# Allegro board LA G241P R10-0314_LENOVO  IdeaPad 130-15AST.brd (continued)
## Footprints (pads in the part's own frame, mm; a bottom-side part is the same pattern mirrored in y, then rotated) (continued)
A6-9200E_BGA_769P-T
  round 0.406 smd: A2(0.6,0) A3(1.35,0) A39(21.25,0) A40(22,0) AA4(2.1,-11.3) AA5(2.9,-11.3) AA7(3.7,-11.3) AA8(4.5,-11.3) AA10(5.3,-11.3) AA11(6.3,-11.3) AA13(7.3,-11.3) AA15(8.3,-11.3) AA17(9.3,-11.3) AA19(10.3,-11.3) AA21(11.3,-11.3) AA23(12.3,-11.3) AA25(13.3,-11.3) AA27(14.3,-11.3) AA29(15.3,-11.3) AA31(16.3,-11.3) AA32(17.3,-11.3) AA34(18.1,-11.3) AA35(18.9,-11.3) AA37(19.7,-11.3) AA38(20.5,-11.3) AC4(2.1,-12.4) AC5(2.9,-12.4) AC7(3.7,-12.4) AC8(4.5,-12.4) AC10(5.3,-12.4) AC11(6.3,-12.3) AC13(7.3,-12.3) AC15(8.3,-12.3) AC17(9.3,-12.3) AC19(10.3,-12.3) AC21(11.3,-12.3) AC23(12.3,-12.3) AC25(13.3,-12.3) AC27(14.3,-12.3) AC29(15.3,-12.3) AC31(16.3,-12.3) AC32(17.3,-12.4) AC34(18.1,-12.4) AC35(18.9,-12.4) AC37(19.7,-12.4) AC38(20.5,-12.4) AE4(2.1,-13.5) AE5(2.9,-13.5) AE7(3.7,-13.5) AE8(4.5,-13.5) AE10(5.3,-13.5) AE11(6.3,-13.3) AE13(7.3,-13.3) AE15(8.3,-13.3) AE17(9.3,-13.3) AE19(10.3,-13.3) AE21(11.3,-13.3) AE23(12.3,-13.3) AE25(13.3,-13.3) AE27(14.3,-13.3) AE29(15.3,-13.3) AE31(16.3,-13.3) AE32(17.3,-13.5) AE34(18.1,-13.5) AE35(18.9,-13.5) AE37(19.7,-13.5) AE38(20.5,-13.5) AG4(2.1,-14.6) AG5(2.9,-14.6) AG7(3.7,-14.6) AG8(4.5,-14.6) AG10(5.3,-14.6) AG11(6.3,-14.3) AG13(7.3,-14.3) AG15(8.3,-14.3) AG17(9.3,-14.3) AG19(10.3,-14.3) AG21(11.3,-14.3) AG23(12.3,-14.3) AG25(13.3,-14.3) AG27(14.3,-14.3) AG29(15.3,-14.3) AG31(16.3,-14.3) AG32(17.3,-14.6) AG34(18.1,-14.6) AG35(18.9,-14.6) AG37(19.7,-14.6) AG38(20.5,-14.6) AJ4(2.1,-15.7) AJ5(2.9,-15.7) AJ7(3.7,-15.7) AJ8(4.5,-15.7) AJ10(5.3,-15.7) AJ11(6.3,-15.3) AJ13(7.3,-15.3) AJ15(8.3,-15.3) AJ17(9.3,-15.3) AJ19(10.3,-15.3) AJ21(11.3,-15.3) AJ23(12.3,-15.3) AJ25(13.3,-15.3) AJ27(14.3,-15.3) AJ29(15.3,-15.3) AJ31(16.3,-15.3) AJ32(17.3,-15.7) AJ34(18.1,-15.7) AJ35(18.9,-15.7) AJ37(19.7,-15.7) AJ38(20.5,-15.7) AL4(2.1,-16.8) AL5(2.9,-16.8) AL7(3.7,-16.8) AL8(4.5,-16.8) AL10(5.3,-16.8) AL11(6.3,-16.3) AL13(7.3,-16.3) AL15(8.3,-16.3) AL17(9.3,-16.3) AL19(10.3,-16.3) AL21(11.3,-16.3) AL23(12.3,-16.3) AL25(13.3,-16.3) AL27(14.3,-16.3) AL29(15.3,-16.3) AL31(16.3,-16.3) AL32(17.3,-16.8) AL34(18.1,-16.8) AL35(18.9,-16.8) AL37(19.7,-16.8) AL38(20.5,-16.8) AM11(5.8,-17.3) AM13(6.9,-17.3) AM15(8,-17.3) AM17(9.1,-17.3) AM19(10.2,-17.3) AM21(11.3,-17.3) AM23(12.4,-17.3) AM25(13.5,-17.3) AM27(14.6,-17.3) AM29(15.7,-17.3) AM31(16.8,-17.3) AN4(2.1,-17.9) AN5(2.9,-17.9) AN7(3.7,-17.9) AN8(4.5,-17.9) AN34(18.1,-17.9) AN35(18.9,-17.9) AN37(19.7,-17.9) AN38(20.5,-17.9) AP11(5.8,-18.1) AP13(6.9,-18.1) AP15(8,-18.1) AP17(9.1,-18.1) AP19(10.2,-18.1) AP21(11.3,-18.1) AP23(12.4,-18.1) AP25(13.5,-18.1) AP27(14.6,-18.1) AP29(15.7,-18.1) AP31(16.8,-18.1) AR4(2.1,-19) AR5(2.9,-19) AR7(3.7,-19) AR11(5.8,-18.9) AR13(6.9,-18.9) AR15(8,-18.9) AR17(9.1,-18.9) AR19(10.2,-18.9) AR21(11.3,-18.9) AR23(12.4,-18.9) AR25(13.5,-18.9) AR27(14.6,-18.9) AR29(15.7,-18.9) AR31(16.8,-18.9) AR35(18.9,-19) AR37(19.7,-19) AR38(20.5,-19) AU4(2.1,-20.1) AU7(3.6,-19.7) AU9(4.7,-19.7) AU11(5.8,-19.7) AU13(6.9,-19.7) AU15(8,-19.7) AU17(9.1,-19.7) AU19(10.2,-19.7) AU21(11.3,-19.7) AU23(12.4,-19.7) AU25(13.5,-19.7) AU27(14.6,-19.7) AU29(15.7,-19.7) AU31(16.8,-19.7) AU33(17.9,-19.7) AU35(19,-19.7) AU38(20.5,-20.1) AV7(3.6,-20.5) AV9(4.7,-20.5) AV11(5.8,-20.5) AV13(6.9,-20.5) AV15(8,-20.5) AV17(9.1,-20.5) AV19(10.2,-20.5) AV21(11.3,-20.5) AV23(12.4,-20.5) AV25(13.5,-20.5) AV27(14.6,-20.5) AV29(15.7,-20.5) AV31(16.8,-20.5) AV33(17.9,-20.5) AV35(19,-20.5) AW1(0,-21.25) AW41(22.6,-21.25) AY1(0,-22) AY2(0.7,-21.9) AY40(21.9,-21.9) AY41(22.6,-22) B1(0,-0.6) B2(0.7,-0.7) B40(21.9,-0.7) B41(22.6,-0.6) BA2(0.6,-22.6) BA3(1.35,-22.6) BA39(21.25,-22.6) BA40(22,-22.6) C1(0,-1.35) C41(22.6,-1.35) D7(3.6,-2.1) D9(4.7,-2.1) D11(5.8,-2.1) D13(6.9,-2.1) D15(8,-2.1) D17(9.1,-2.1) D19(10.2,-2.1) D21(11.3,-2.1) D23(12.4,-2.1) D25(13.5,-2.1) D27(14.6,-2.1) D29(15.7,-2.1) D31(16.8,-2.1) D33(17.9,-2.1) D35(19,-2.1) E4(2.1,-2.5) E7(3.6,-2.9) E9(4.7,-2.9) E11(5.8,-2.9) E13(6.9,-2.9) E15(8,-2.9) E17(9.1,-2.9) E19(10.2,-2.9) E21(11.3,-2.9) E23(12.4,-2.9) E25(13.5,-2.9) E27(14.6,-2.9) E29(15.7,-2.9) E31(16.8,-2.9) E33(17.9,-2.9) E35(19,-2.9) E38(20.5,-2.5) G4(2.1,-3.6) G5(2.9,-3.6) G7(3.7,-3.6) G11(5.8,-3.7) G13(6.9,-3.7) G15(8,-3.7) G17(9.1,-3.7) G19(10.2,-3.7) G21(11.3,-3.7) G23(12.4,-3.7) G25(13.5,-3.7) G27(14.6,-3.7) G29(15.7,-3.7) G31(16.8,-3.7) G35(18.9,-3.6) G37(19.7,-3.6) G38(20.5,-3.6) H11(5.8,-4.5) H13(6.9,-4.5) H15(8,-4.5) H17(9.1,-4.5) H19(10.2,-4.5) H21(11.3,-4.5) H23(12.4,-4.5) H25(13.5,-4.5) H27(14.6,-4.5) H29(15.7,-4.5) H31(16.8,-4.5) J4(2.1,-4.7) J5(2.9,-4.7) J7(3.7,-4.7) J8(4.5,-4.7) J34(18.1,-4.7) J35(18.9,-4.7) J37(19.7,-4.7) J38(20.5,-4.7) K11(5.8,-5.3) K13(6.9,-5.3) K15(8,-5.3) K17(9.1,-5.3) K19(10.2,-5.3) K21(11.3,-5.3) K23(12.4,-5.3) K25(13.5,-5.3) K27(14.6,-5.3) K29(15.7,-5.3) K31(16.8,-5.3) L4(2.1,-5.8) L5(2.9,-5.8) L7(3.7,-5.8) L8(4.5,-5.8) L10(5.3,-5.8) L11(6.3,-6.3) L13(7.3,-6.3) L15(8.3,-6.3) L17(9.3,-6.3) L19(10.3,-6.3) L21(11.3,-6.3) L23(12.3,-6.3) L25(13.3,-6.3) L27(14.3,-6.3) L29(15.3,-6.3) L31(16.3,-6.3) L32(17.3,-5.8) L34(18.1,-5.8) L35(18.9,-5.8) L37(19.7,-5.8) L38(20.5,-5.8) N4(2.1,-6.9) N5(2.9,-6.9) N7(3.7,-6.9) N8(4.5,-6.9) N10(5.3,-6.9) N11(6.3,-7.3) N13(7.3,-7.3) N15(8.3,-7.3) N17(9.3,-7.3) N19(10.3,-7.3) N21(11.3,-7.3) N23(12.3,-7.3) N25(13.3,-7.3) N27(14.3,-7.3) N29(15.3,-7.3) N31(16.3,-7.3) N32(17.3,-6.9) N34(18.1,-6.9) N35(18.9,-6.9) N37(19.7,-6.9) N38(20.5,-6.9) R4(2.1,-8) R5(2.9,-8) R7(3.7,-8) R8(4.5,-8) R10(5.3,-8) R11(6.3,-8.3) R13(7.3,-8.3) R15(8.3,-8.3) R17(9.3,-8.3) R19(10.3,-8.3) R21(11.3,-8.3) R23(12.3,-8.3) R25(13.3,-8.3) R27(14.3,-8.3) R29(15.3,-8.3) R31(16.3,-8.3) R32(17.3,-8) R34(18.1,-8) R35(18.9,-8) R37(19.7,-8) R38(20.5,-8) U4(2.1,-9.1) U5(2.9,-9.1) U7(3.7,-9.1) U8(4.5,-9.1) U10(5.3,-9.1) U11(6.3,-9.3) U13(7.3,-9.3) U15(8.3,-9.3) U17(9.3,-9.3) U19(10.3,-9.3) U21(11.3,-9.3) U23(12.3,-9.3) U25(13.3,-9.3) U27(14.3,-9.3) U29(15.3,-9.3) U31(16.3,-9.3) U32(17.3,-9.1) U34(18.1,-9.1) U35(18.9,-9.1) U37(19.7,-9.1) U38(20.5,-9.1) W4(2.1,-10.2) W5(2.9,-10.2) W7(3.7,-10.2) W8(4.5,-10.2) W10(5.3,-10.2) W11(6.3,-10.3) W13(7.3,-10.3) W15(8.3,-10.3) W17(9.3,-10.3) W19(10.3,-10.3) W21(11.3,-10.3) W23(12.3,-10.3) W25(13.3,-10.3) W27(14.3,-10.3) W29(15.3,-10.3) W31(16.3,-10.3) W32(17.3,-10.2) W34(18.1,-10.2) W35(18.9,-10.2) W37(19.7,-10.2) W38(20.5,-10.2)
  round 0.305 smd: A4(1.95,-0.35) A5(2.5,0) A6(3.05,-0.35) A7(3.6,0) A8(4.15,-0.35) A9(4.7,0) A10(5.25,-0.35) A11(5.8,0) A12(6.35,-0.35) A13(6.9,0) A14(7.45,-0.35) A15(8,0) A16(8.55,-0.35) A17(9.1,0) A18(9.65,-0.35) A19(10.2,0) A20(10.75,-0.35) A21(11.3,0) A22(11.85,-0.35) A23(12.4,0) A24(12.95,-0.35) A25(13.5,0) A26(14.05,-0.35) A27(14.6,0) A28(15.15,-0.35) A29(15.7,0) A30(16.25,-0.35) A31(16.8,0) A32(17.35,-0.35) A33(17.9,0) A34(18.45,-0.35) A35(19,0) A36(19.55,-0.35) A37(20.1,0) A38(20.65,-0.35) AA1(0,-11.3) AA2(0.7,-11.3) AA3(1.4,-11.3) AA39(21.2,-11.3) AA40(21.9,-11.3) AA41(22.6,-11.3) AB1(0.35,-11.85) AB2(1.05,-11.85) AB40(21.55,-11.85) AB41(22.25,-11.85) AC1(0,-12.4) AC2(0.7,-12.4) AC3(1.4,-12.4) AC39(21.2,-12.4) AC40(21.9,-12.4) AC41(22.6,-12.4) AD1(0.35,-12.95) AD2(1.05,-12.95) AD40(21.55,-12.95) AD41(22.25,-12.95) AE1(0,-13.5) AE2(0.7,-13.5) AE3(1.4,-13.5) AE39(21.2,-13.5) AE40(21.9,-13.5) AE41(22.6,-13.5) AF1(0.35,-14.05) AF2(1.05,-14.05) AF40(21.55,-14.05) AF41(22.25,-14.05) AG1(0,-14.6) AG2(0.7,-14.6) AG3(1.4,-14.6) AG39(21.2,-14.6) AG40(21.9,-14.6) AG41(22.6,-14.6) AH1(0.35,-15.15) AH2(1.05,-15.15) AH40(21.55,-15.15) AH41(22.25,-15.15) AJ1(0,-15.7) AJ2(0.7,-15.7) AJ3(1.4,-15.7) AJ39(21.2,-15.7) AJ40(21.9,-15.7) AJ41(22.6,-15.7) AK1(0.35,-16.25) AK2(1.05,-16.25) AK40(21.55,-16.25) AK41(22.25,-16.25) AL1(0,-16.8) AL2(0.7,-16.8) AL3(1.4,-16.8) AL39(21.2,-16.8) AL40(21.9,-16.8) AL41(22.6,-16.8) AM1(0.35,-17.35) AM2(1.05,-17.35) AM40(21.55,-17.35) AM41(22.25,-17.35) AN1(0,-17.9) AN2(0.7,-17.9) AN3(1.4,-17.9) AN39(21.2,-17.9) AN40(21.9,-17.9) AN41(22.6,-17.9) AP1(0.35,-18.45) AP2(1.05,-18.45) AP40(21.55,-18.45) AP41(22.25,-18.45) AR1(0,-19) AR2(0.7,-19) AR3(1.4,-19) AR39(21.2,-19) AR40(21.9,-19) AR41(22.6,-19) AT1(0.35,-19.55) AT2(1.05,-19.55) AT40(21.55,-19.55) AT41(22.25,-19.55) AU1(0,-20.1) AU2(0.7,-20.1) AU3(1.4,-20.1) AU39(21.2,-20.1) AU40(21.9,-20.1) AU41(22.6,-20.1) AV1(0.35,-20.65) AV2(1.05,-20.65) AV40(21.55,-20.65) AV41(22.25,-20.65) AW2(0.7,-21.2) AW3(1.4,-21.2) AW5(2.5,-21.2) AW7(3.6,-21.2) AW9(4.7,-21.2) AW11(5.8,-21.2) AW13(6.9,-21.2) AW15(8,-21.2) AW17(9.1,-21.2) AW19(10.2,-21.2) AW21(11.3,-21.2) AW23(12.4,-21.2) AW25(13.5,-21.2) AW27(14.6,-21.2) AW29(15.7,-21.2) AW31(16.8,-21.2) AW33(17.9,-21.2) AW35(19,-21.2) AW37(20.1,-21.2) AW39(21.2,-21.2) AW40(21.9,-21.2) AY3(1.4,-21.9) AY4(1.95,-21.55) AY5(2.5,-21.9) AY6(3.05,-21.55) AY7(3.6,-21.9) AY8(4.15,-21.55) AY9(4.7,-21.9) AY10(5.25,-21.55) AY11(5.8,-21.9) AY12(6.35,-21.55) AY13(6.9,-21.9) AY14(7.45,-21.55) AY15(8,-21.9) AY16(8.55,-21.55) AY17(9.1,-21.9) AY18(9.65,-21.55) AY19(10.2,-21.9) AY20(10.75,-21.55) AY21(11.3,-21.9) AY22(11.85,-21.55) AY23(12.4,-21.9) AY24(12.95,-21.55) AY25(13.5,-21.9) AY26(14.05,-21.55) AY27(14.6,-21.9) AY28(15.15,-21.55) AY29(15.7,-21.9) AY30(16.25,-21.55) AY31(16.8,-21.9) AY32(17.35,-21.55) AY33(17.9,-21.9) AY34(18.45,-21.55) AY35(19,-21.9) AY36(19.55,-21.55) AY37(20.1,-21.9) AY38(20.65,-21.55) AY39(21.2,-21.9) B3(1.4,-0.7) B4(1.95,-1.05) B5(2.5,-0.7) B6(3.05,-1.05) B7(3.6,-0.7) B8(4.15,-1.05) B9(4.7,-0.7) B10(5.25,-1.05) B11(5.8,-0.7) B12(6.35,-1.05) B13(6.9,-0.7) B14(7.45,-1.05) B15(8,-0.7) B16(8.55,-1.05) B17(9.1,-0.7) B18(9.65,-1.05) B19(10.2,-0.7) B20(10.75,-1.05) B21(11.3,-0.7) B22(11.85,-1.05) B23(12.4,-0.7) B24(12.95,-1.05) B25(13.5,-0.7) B26(14.05,-1.05) B27(14.6,-0.7) B28(15.15,-1.05) B29(15.7,-0.7) B30(16.25,-1.05) B31(16.8,-0.7) B32(17.35,-1.05) B33(17.9,-0.7) B34(18.45,-1.05) B35(19,-0.7) B36(19.55,-1.05) B37(20.1,-0.7) B38(20.65,-1.05) B39(21.2,-0.7) BA4(1.95,-22.25) BA5(2.5,-22.6) BA6(3.05,-22.25) BA7(3.6,-22.6) BA8(4.15,-22.25) BA9(4.7,-22.6) BA10(5.25,-22.25) BA11(5.8,-22.6) BA12(6.35,-22.25) BA13(6.9,-22.6) BA14(7.45,-22.25) BA15(8,-22.6) BA16(8.55,-22.25) BA17(9.1,-22.6) BA18(9.65,-22.25) BA19(10.2,-22.6) BA20(10.75,-22.25) BA21(11.3,-22.6) BA22(11.85,-22.25) BA23(12.4,-22.6) BA24(12.95,-22.25) BA25(13.5,-22.6) BA26(14.05,-22.25) BA27(14.6,-22.6) BA28(15.15,-22.25) BA29(15.7,-22.6) BA30(16.25,-22.25) BA31(16.8,-22.6) BA32(17.35,-22.25) BA33(17.9,-22.6) BA34(18.45,-22.25) BA35(19,-22.6) BA36(19.55,-22.25) BA37(20.1,-22.6) BA38(20.65,-22.25) C2(0.7,-1.4) C3(1.4,-1.4) C5(2.5,-1.4) C7(3.6,-1.4) C9(4.7,-1.4) C11(5.8,-1.4) C13(6.9,-1.4) C15(8,-1.4) C17(9.1,-1.4) C19(10.2,-1.4) C21(11.3,-1.4) C23(12.4,-1.4) C25(13.5,-1.4) C27(14.6,-1.4) C29(15.7,-1.4) C31(16.8,-1.4) C33(17.9,-1.4) C35(19,-1.4) C37(20.1,-1.4) C39(21.2,-1.4) C40(21.9,-1.4) D1(0.35,-1.95) D2(1.05,-1.95) D40(21.55,-1.95) D41(22.25,-1.95) E1(0,-2.5) E2(0.7,-2.5) E3(1.4,-2.5) E39(21.2,-2.5) E40(21.9,-2.5) E41(22.6,-2.5) F1(0.35,-3.05) F2(1.05,-3.05) F40(21.55,-3.05) F41(22.25,-3.05) G1(0,-3.6) G2(0.7,-3.6) G3(1.4,-3.6) G39(21.2,-3.6) G40(21.9,-3.6) G41(22.6,-3.6) H1(0.35,-4.15) H2(1.05,-4.15) H40(21.55,-4.15) H41(22.25,-4.15) J1(0,-4.7) J2(0.7,-4.7) J3(1.4,-4.7) J39(21.2,-4.7) J40(21.9,-4.7) J41(22.6,-4.7) K1(0.35,-5.25) K2(1.05,-5.25) K40(21.55,-5.25) K41(22.25,-5.25) L1(0,-5.8) L2(0.7,-5.8) L3(1.4,-5.8) L39(21.2,-5.8) L40(21.9,-5.8) L41(22.6,-5.8) M1(0.35,-6.35) M2(1.05,-6.35) M40(21.55,-6.35) M41(22.25,-6.35) N1(0,-6.9) N2(0.7,-6.9) N3(1.4,-6.9) N39(21.2,-6.9) N40(21.9,-6.9) N41(22.6,-6.9) P1(0.35,-7.45) P2(1.05,-7.45) P40(21.55,-7.45) P41(22.25,-7.45) R1(0,-8) R2(0.7,-8) R3(1.4,-8) R39(21.2,-8) R40(21.9,-8) R41(22.6,-8) T1(0.35,-8.55) T2(1.05,-8.55) T40(21.55,-8.55) T41(22.25,-8.55) U1(0,-9.1) U2(0.7,-9.1) U3(1.4,-9.1) U39(21.2,-9.1) U40(21.9,-9.1) U41(22.6,-9.1) V1(0.35,-9.65) V2(1.05,-9.65) V40(21.55,-9.65) V41(22.25,-9.65) W1(0,-10.2) W2(0.7,-10.2) W3(1.4,-10.2) W39(21.2,-10.2) W40(21.9,-10.2) W41(22.6,-10.2) Y1(0.35,-10.75) Y2(1.05,-10.75) Y40(21.55,-10.75) Y41(22.25,-10.75)
ACES_50271-0020N-001_2P
  oval 0.787x1.6 smd: 1(0,0) 2(1.25,0)
  rect 2.108x2.997 smd: 3(3.8,-2.9) 4(-2.55,-2.9)
ACES_50271-0040N-001_4P
  oval 0.787x1.6 smd: 1(0,0) 2(-1.25,0) 3(-2.5,0) 4(-3.75,0)
  rect 2.108x2.997 smd: 5(2.55,-2.9) 6(-6.3,-2.9)
ACES_50278-00401-001_4P
  oval 0.787x1.905 smd: 1(0,0) 2(1.25,0) 3(2.5,0) 4(3.75,0)
  rect 1.295x3.353 smd: 5(-2.85,-4.925) 6(6.6,-4.925)
ACES_51522-00601-001_6P
  oval 0.305x1.295 smd: 1(0,0) 2(0.5,0) 3(1,0) 4(1.5,0) 5(2,0) 6(2.5,0)
  rect 2.489x1.905 smd: 7(-2.15,-3.3) 8(4.65,-3.3)
ACES_51530-01001-P01_10P
  oval 0.305x1.143 smd: 1(0,0) 2(-0.5,0) 3(-1,0) 4(-1.5,0) 5(-2,0) 6(-2.5,0) 7(-3,0) 8(-3.5,0) 9(-4,0) 10(-4.5,0)
  rect 0.787x2.007 smd: 11(1.7,-3.325) 12(-6.2,-3.325)
ACES_87242-3001-09_30P
  oval 0.61x1.499 smd: 1(0,0) 2(0,-6.1) 3(1,0) 4(1,-6.1) 5(2,0) 6(2,-6.1) 7(3,0) 8(3,-6.1) 9(4,0) 10(4,-6.1) 11(5,0) 12(5,-6.1) 13(6,0) 14(6,-6.1) 15(7,0) 16(7,-6.1) 17(8,0) 18(8,-6.1) 19(9,0) 20(9,-6.1) 21(10,0) 22(10,-6.1) 23(11,0) 24(11,-6.1) 25(12,0) 26(12,-6.1) 27(13,0) 28(13,-6.1) 29(14,0) 30(14,-6.1)
  rect 1.499x2.007 smd: 31(-2,-4.6) 32(16,-4.6)
ACON_HMRA4-AK120C_19P
  round 0.813 hole 0.559: 1(0,0) 2(0.5,1.55) 3(1,0) 4(1.5,1.55) 5(2,0) 6(2.5,1.55) 7(3,0) 8(3.5,1.55) 9(4,0) 10(4.5,1.55) 11(5,0) 12(5.5,1.55) 13(6,0) 14(6.5,1.55) 15(7,0) 16(7.5,1.55) 17(8,0) 18(8.5,1.55) 19(9,0)
  oval 1.499x2.21 hole 0.889x1.6: 20(-2.75,1.7) 21(-4.65,-6.5) 22(11.75,1.7) 23(13.65,-7.75)
ACON_TARAN-9R1391_9P
  round 0.991 hole 0.711: 1(0,0) 2(-2.5,0) 3(-4.5,0) 4(-7,0) 5(-7.5,-1.5) 6(-5.5,-1.5) 7(-3.5,-1.5) 8(-1.5,-1.5) 9(0.5,-1.5)
  oval 1.397x3.2 hole 0.787x2.591: 10(-11.35,-2.38) 12(4.35,-2.38)
  oval 1.397x2.388 hole 0.787x1.803: 11(-11.35,-9.48) 13(4.35,-9.48)
ALC3240-CG_MQFN40_5X5-S
  oval 0.889x0.203 smd: 1(0,0) 2(0,-0.4) 3(0,-0.8) 4(0,-1.2) 5(0,-1.6) 6(0,-2) 7(0,-2.4) 8(0,-2.8) 9(0,-3.2) 10(0,-3.6) 21(5.1,-3.6) 22(5.1,-3.2) 23(5.1,-2.8) 24(5.1,-2.4) 25(5.1,-2) 26(5.1,-1.6) 27(5.1,-1.2) 28(5.1,-0.8) 29(5.1,-0.4) 30(5.1,0)
  oval 0.203x0.889 smd: 11(0.75,-4.35) 12(1.15,-4.35) 13(1.55,-4.35) 14(1.95,-4.35) 15(2.35,-4.35) 16(2.75,-4.35) 17(3.15,-4.35) 18(3.55,-4.35) 19(3.95,-4.35) 20(4.35,-4.35) 31(4.35,0.75) 32(3.95,0.75) 33(3.55,0.75) 34(3.15,0.75) 35(2.75,0.75) 36(2.35,0.75) 37(1.95,0.75) 38(1.55,0.75) 39(1.15,0.75) 40(0.75,0.75)
  rect 3.607x3.607 smd: 41(2.55,-1.8)
AO3416_SOT23-3
  oval 1.016x1.524 smd: 1(0,0) 2(0.965,2.083) 3(-0.965,2.083)
AO4430L_SO8
  oval 0.635x1.854 smd: 1(0,0) 2(1.27,0) 3(2.54,0) 4(3.81,0) 5(3.81,5.165) 6(2.54,5.165) 7(1.27,5.165) 8(0,5.165)
AON6380_DFN5X6-8-5
  oval 0.508x0.838 smd: 1(0,0) 2(1.27,0) 3(2.54,0) 4(3.81,0)
  custom 1.15x1.15 smd: 5(1.905,3.69)
AON6962_DFN5X6D-8-7
  oval 0.66x0.635 smd: 1(0,0) 3(3.81,5.67) 4(2.54,5.67) 5(1.27,5.67) 6(0,5.67)
  custom 0.485x0.485 smd: 2(1.905,0.655)
  rect 3.988x2.667 smd: 7(1.905,3.63)
AON7408L_DFN8-5
  oval 0.406x0.991 smd: 1(0,0) 2(0.66,0) 3(1.32,0) 4(1.98,0)
  custom 0.559x0.559 smd: 5(0.99,2.247)
AON7506_DFN3X3-8-5
  oval 0.406x0.991 smd: 1(0,0) 2(0.66,0) 3(1.32,0) 4(1.98,0)
  custom 0.559x0.559 smd: 5(0.99,2.247)
AON7506_DFN33-8-5
  oval 0.406x0.991 smd: 1(0,0) 2(0.66,0) 3(1.32,0) 4(1.98,0)
  custom 0.559x0.559 smd: 5(0.99,2.247)
AON7752_DFN3X3EP8-5
  oval 0.406x0.991 smd: 1(0,0) 2(0.66,0) 3(1.32,0) 4(1.98,0)
  custom 0.559x0.559 smd: 5(0.99,2.247)
AOZ1336_DFN8_2X2
  oval 0.254x0.787 smd: 1(0,0) 2(0.5,0) 3(1,0) 4(1.5,0) 5(1.5,2.2) 6(1,2.2) 7(0.5,2.2) 8(0,2.2)
  rect 1.499x0.889 smd: 9(0.75,1.1)
AP2138N-1P5TRG1_SOT23-3
  oval 1.016x1.524 smd: 1(0,0) 2(0.965,2.083) 3(-0.965,2.083)
AP2330W-7_SC59-3
  oval 0.787x0.991 smd: 1(0,0) 2(-0.95,-2.4) 3(0.95,-2.4)
APL5336KAI-TRL_SOP8P8
  oval 0.635x1.854 smd: 1(0,0) 2(1.27,0) 3(2.54,0) 4(3.81,0) 5(3.81,5.165) 6(2.54,5.165) 7(1.27,5.165) 8(0,5.165)
  rect 2.87x2.489 smd: 9(1.905,2.582)
AS393MTR-G1_SO8
  oval 0.635x1.651 smd: 1(0,0) 2(1.27,0) 3(2.54,0) 4(3.81,0) 5(3.81,5.375) 6(2.54,5.375) 7(1.27,5.375) 8(0,5.375)
AZC099-04SPR7G_SOT23-6
  oval 0.559x1.092 smd: 1(0,0) 2(0.95,0) 3(1.9,0) 4(1.9,2.5) 5(0.95,2.5) 6(0,2.5)
BS4200N-C-LV_SMB-F2
  rect 2.159x2.743 smd: 1(0,0) 2(4.42,0)
C_5X4P5
  oval 2.997x1.6 smd: 1(0,0) 2(-4.4,0)
C_6P3X6
  oval 3.505x1.6 smd: 1(0,0) 2(5.6,0)
C_0201
  rect 0.381x0.356 smd: 1(0,0) 2(0.584,0)
C_0402
  rect 0.508x0.584 smd: 1(0,0) 2(0.914,0)
C_0603
  rect 0.635x0.889 smd: 1(0,0) 2(1.397,0)
C_0805
  rect 0.813x1.397 smd: 1(0,0) 2(1.702,0)
C_D2
  rect 2.388x2.794 smd: 1(0,0) 2(6.4,0)
C_D3
  rect 2.388x2.794 smd: 1(0,0) 2(6.4,0)
C_MP6VLPS220MC4R2
  oval 3.505x1.6 smd: 1(0,0) 2(-5.6,0)
C_OVH561M0ETR-0606
  oval 3.505x1.6 smd: 1(0,0) 2(-5.4,0)
CH751H-40PT_SOD323-2
  rect 0.711x0.711 smd: 1(0,0) 2(2.33,0)
D_SOD323-2
  rect 0.787x0.889 smd: 1(0,0) 2(2.14,0)
DEREN_40-42271-26001RHF_260P-T
  round 1.6 hole 1.6 unplated: (-1.025,4.1)
  round 1.092 hole 1.092 unplated: (67.775,4.1)
  oval 0.305x1.753 smd: 1(0,0) 2(0.25,8.2) 3(0.5,0) 4(0.75,8.2) 5(1,0) 6(1.25,8.2) 7(1.5,0) 8(1.75,8.2) 9(2,0) 10(2.25,8.2) 11(2.5,0) 12(2.75,8.2) 13(3,0) 14(3.25,8.2) 15(3.5,0) 16(3.75,8.2) 17(4,0) 18(4.25,8.2) 19(4.5,0) 20(4.75,8.2) 21(5,0) 22(5.25,8.2) 23(5.5,0) 24(5.75,8.2) 25(6,0) 26(6.25,8.2) 27(6.5,0) 28(6.75,8.2) 29(7,0) 30(7.25,8.2) 31(7.5,0) 32(7.75,8.2) 33(8,0) 34(8.25,8.2) 35(8.5,0) 36(8.75,8.2) 37(9,0) 38(9.25,8.2) 39(9.5,0) 40(9.75,8.2) 41(10,0) 42(10.25,8.2) 43(10.5,0) 44(10.75,8.2) 45(11,0) 46(11.25,8.2) 47(11.5,0) 48(11.75,8.2) 49(12,0) 50(12.25,8.2) 51(12.5,0) 52(12.75,8.2) 53(13,0) 54(13.25,8.2) 55(13.5,0) 56(13.75,8.2) 57(14,0) 58(14.25,8.2) 59(14.5,0) 60(14.75,8.2) 61(15,0) 62(15.25,8.2) 63(15.5,0) 64(15.75,8.2) 65(16,0) 66(16.25,8.2) 67(16.5,0) 68(16.75,8.2) 69(17,0) 70(17.25,8.2) 71(17.5,0) 72(17.75,8.2) 73(18,0) 74(18.25,8.2) 75(18.5,0) 76(18.75,8.2) 77(19,0) 78(19.25,8.2) 79(19.5,0) 80(19.75,8.2) 81(20,0) 82(20.25,8.2) 83(20.5,0) 84(20.75,8.2) 85(21,0) 86(21.25,8.2) 87(21.5,0) 88(21.75,8.2) 89(22,0) 90(22.25,8.2) 91(22.5,0) 92(22.75,8.2) 93(23,0) 94(23.25,8.2) 95(23.5,0) 96(23.75,8.2) 97(24,0) 98(24.25,8.2) 99(24.5,0) 100(24.75,8.2) 101(25,0) 102(25.25,8.2) 103(25.5,0) 104(25.75,8.2) 105(26,0) 106(26.25,8.2) 107(26.5,0) 108(26.75,8.2) 109(27,0) 110(27.25,8.2) 111(27.5,0) 112(27.75,8.2) 113(28,0) 114(28.25,8.2) 115(28.5,0) 116(28.75,8.2) 117(29,0) 118(29.25,8.2) 119(29.5,0) 120(29.75,8.2) 121(30,0) 122(30.25,8.2) 123(30.5,0) 124(30.75,8.2) 125(31,0) 126(31.25,8.2) 127(31.5,0) 128(31.75,8.2) 129(32,0) 130(32.25,8.2) 131(32.5,0) 132(32.75,8.2) 133(33,0) 134(33.25,8.2) 135(33.5,0) 136(33.75,8.2) 137(34,0) 138(34.25,8.2) 139(34.5,0) 140(34.75,8.2) 141(35,0) 142(35.25,8.2) 143(35.5,0) 144(35.75,8.2) 145(38,0) 146(38.25,8.2) 147(38.5,0) 148(38.75,8.2) 149(39,0) 150(39.25,8.2) 151(39.5,0) 152(39.75,8.2) 153(40,0) 154(40.25,8.2) 155(40.5,0) 156(40.75,8.2) 157(41,0) 158(41.25,8.2) 159(41.5,0) 160(41.75,8.2) 161(42,0) 162(42.25,8.2) 163(42.5,0) 164(42.75,8.2) 165(43,0) 166(43.25,8.2) 167(43.5,0) 168(43.75,8.2) 169(44,0) 170(44.25,8.2) 171(44.5,0) 172(44.75,8.2) 173(45,0) 174(45.25,8.2) 175(45.5,0) 176(45.75,8.2) 177(46,0) 178(46.25,8.2) 179(46.5,0) 180(46.75,8.2) 181(47,0) 182(47.25,8.2) 183(47.5,0) 184(47.75,8.2) 185(48,0) 186(48.25,8.2) 187(48.5,0) 188(48.75,8.2) 189(49,0) 190(49.25,8.2) 191(49.5,0) 192(49.75,8.2) 193(50,0) 194(50.25,8.2) 195(50.5,0) 196(50.75,8.2) 197(51,0) 198(51.25,8.2) 199(51.5,0) 200(51.75,8.2) 201(52,0) 202(52.25,8.2) 203(52.5,0) 204(52.75,8.2) 205(53,0) 206(53.25,8.2) 207(53.5,0) 208(53.75,8.2) 209(54,0) 210(54.25,8.2) 211(54.5,0) 212(54.75,8.2) 213(55,0) 214(55.25,8.2) 215(55.5,0) 216(55.75,8.2) 217(56,0) 218(56.25,8.2) 219(56.5,0) 220(56.75,8.2) 221(57,0) 222(57.25,8.2) 223(57.5,0) 224(57.75,8.2) 225(58,0) 226(58.25,8.2) 227(58.5,0) 228(58.75,8.2) 229(59,0) 230(59.25,8.2) 231(59.5,0) 232(59.75,8.2) 233(60,0) 234(60.25,8.2) 235(60.5,0) 236(60.75,8.2) 237(61,0) 238(61.25,8.2) 239(61.5,0) 240(61.75,8.2) 241(62,0) 242(62.25,8.2) 243(62.5,0) 244(62.75,8.2) 245(63,0) 246(63.25,8.2) 247(63.5,0) 248(63.75,8.2) 249(64,0) 250(64.25,8.2) 251(64.5,0) 252(64.75,8.2) 253(65,0) 254(65.25,8.2) 255(65.5,0) 256(65.75,8.2) 257(66,0) 258(66.25,8.2) 259(66.5,0) 260(66.75,8.2)
  rect 3.505x4.597 smd: 261(-0.425,-7.9) 262(67.175,-7.9)
DEREN_43-42095-01111RHF-R_11P
  round 1.194 hole 1.194 unplated: (-18.38,-2.9)
  round 1.702 hole 1.702 unplated: (2.62,-2.9)
  oval 0.991x1.702 smd: 1(0,0) 2(-2.5,0) 3(-5,0) 4(-7.5,0) 5(-10,0) 6(-12.5,0) 7(-15,0) 8(-16.63,0) 9(2.5,0)
  oval 0.711x1.702 smd: 10(-17.93,0) 11(-19.13,0)
  rect 1.499x2.794 smd: 12(4.57,-1.9) 13(-20.53,-1.9) 14(6.77,-16.5) 15(-20.53,-16.5)
DMN66D0LDW-7_SOT363-6
  oval 0.432x0.61 smd: 1(0,0) 2(0.65,0) 3(1.3,0) 4(1.3,1.9) 5(0.65,1.9) 6(0,1.9)
EM5209VF_DFN14_3X2
  oval 0.203x0.711 smd: 1(0,0) 2(0.4,0) 3(0.8,0) 4(1.2,0) 5(1.6,0) 6(2,0) 7(2.4,0) 8(2.4,2) 9(2,2) 10(1.6,2) 11(1.2,2) 12(0.8,2) 13(0.4,2) 14(0,2)
  rect 2.591x0.991 smd: 15(1.2,1)
EMB04N03H_EDFN5X6-8-5
  oval 0.61x1.27 smd: 1(0,0) 2(1.27,0) 3(2.54,0) 4(3.81,0)
  custom 1.105x1.105 smd: 5(1.905,3.715)
F_1206
  rect 1.295x1.803 smd: 1(0,0) 2(2.5,0)
FIDUCIAL_C40M80
  round 1.016 smd: 1(0,0)
G9661MF11U_SO8
  oval 0.635x1.727 smd: 1(0,0) 2(1.27,0) 3(2.54,0) 4(3.81,0) 5(3.81,5.3) 6(2.54,5.3) 7(1.27,5.3) 8(0,5.3)
  rect 3.302x2.413 smd: 9(1.905,2.65)
H_2P5
  round 2.997 hole 2.489: 1(0,0)
H_3P2
  round 3.708 hole 3.2: 1(0,0)
H_3P2N
  round 3.2 hole 3.2 unplated: (0,0)
H_3P3
  round 3.81 hole 3.302: 1(0,0)
H_3P5X2P5N
  oval 3.505x2.489 hole 3.505x2.489 unplated: (0,0)
INPAQ_HCM1012GH900BP_4P
  rect 0.711x0.305 smd: 1(0,0) 2(1.25,0) 3(1.25,-0.5) 4(0,-0.5)
ISL95520HRZ-T_QFN32_4X4
  oval 0.889x0.203 smd: 1(0,0) 2(0,-0.4) 3(0,-0.8) 4(0,-1.2) 5(0,-1.6) 6(0,-2) 7(0,-2.4) 8(0,-2.8) 17(4.1,-2.8) 18(4.1,-2.4) 19(4.1,-2) 20(4.1,-1.6) 21(4.1,-1.2) 22(4.1,-0.8) 23(4.1,-0.4) 24(4.1,0)
  oval 0.203x0.889 smd: 9(0.65,-3.45) 10(1.05,-3.45) 11(1.45,-3.45) 12(1.85,-3.45) 13(2.25,-3.45) 14(2.65,-3.45) 15(3.05,-3.45) 16(3.45,-3.45) 25(3.45,0.65) 26(3.05,0.65) 27(2.65,0.65) 28(2.25,0.65) 29(1.85,0.65) 30(1.45,0.65) 31(1.05,0.65) 32(0.65,0.65)
  rect 2.642x2.642 smd: 33(2.05,-1.4)
JUMP_43X39
  custom 0.191x0.191 smd: 1(0,0) 2(0.914,0)
JUMP_43X79
  custom 0.188x0.188 smd: 1(0,0) 2(1.1,0)
JUMP_43X118
  custom 0.187x0.187 smd: 1(0,0) 2(1.1,0)
JXT_FP257H-032S10M_32P
  oval 0.305x1.295 smd: 1(0,0) 2(0.8,0) 3(1.6,0) 4(2.4,0) 5(3.2,0) 6(4,0) 7(4.8,0) 8(5.6,0) 9(6.4,0) 10(7.2,0) 11(8,0) 12(8.8,0) 13(9.6,0) 14(10.4,0) 15(11.2,0) 16(12,0) 17(12.8,0) 18(13.6,0) 19(14.4,0) 20(15.2,0) 21(16,0) 22(16.8,0) 23(17.6,0) 24(18.4,0) 25(19.2,0) 26(20,0) 27(20.8,0) 28(21.6,0) 29(22.4,0) 30(23.2,0) 31(24,0) 32(24.8,0)
  rect 1.803x2.21 smd: 33(-2.35,-5.65) 34(27.15,-5.65)
K4G80325FB-HC03_FBGA_170P_A39
  round 0.445 smd: A1(0,0) A2(0.8,0) A3(1.6,0) A4(2.4,0) A5(3.2,0) A10(7.201,0) A11(8.001,0) A12(8.801,0) A13(9.601,0) A14(10.401,0) B1(0,-0.8) B2(0.8,-0.8) B3(1.6,-0.8) B4(2.4,-0.8) B5(3.2,-0.8) B10(7.201,-0.8) B11(8.001,-0.8) B12(8.801,-0.8) B13(9.601,-0.8) B14(10.401,-0.8) C1(0,-1.6) C2(0.8,-1.6) C3(1.6,-1.6) C4(2.4,-1.6) C5(3.2,-1.6) C10(7.201,-1.6) C11(8.001,-1.6) C12(8.801,-1.6) C13(9.601,-1.6) C14(10.401,-1.6) D1(0,-2.4) D2(0.8,-2.4) D3(1.6,-2.4) D4(2.4,-2.4) D5(3.2,-2.4) D10(7.201,-2.4) D11(8.001,-2.4) D12(8.801,-2.4) D13(9.601,-2.4) D14(10.401,-2.4) E1(0,-3.2) E2(0.8,-3.2) E3(1.6,-3.2) E4(2.4,-3.2) E5(3.2,-3.2) E10(7.201,-3.2) E11(8.001,-3.2) E12(8.801,-3.2) E13(9.601,-3.2) E14(10.401,-3.2) N1(0,-9.601) N2(0.8,-9.601) N3(1.6,-9.601) N4(2.4,-9.601) N5(3.2,-9.601) N10(7.201,-9.601) N11(8.001,-9.601) N12(8.801,-9.601) N13(9.601,-9.601) N14(10.401,-9.601) P1(0,-10.401) P2(0.8,-10.401) P3(1.6,-10.401) P4(2.4,-10.401) P5(3.2,-10.401) P10(7.201,-10.401) P11(8.001,-10.401) P12(8.801,-10.401) P13(9.601,-10.401) P14(10.401,-10.401) R1(0,-11.201) R2(0.8,-11.201) R3(1.6,-11.201) R4(2.4,-11.201) R5(3.2,-11.201) R10(7.201,-11.201) R11(8.001,-11.201) R12(8.801,-11.201) R13(9.601,-11.201) R14(10.401,-11.201) T1(0,-12.002) T2(0.8,-12.002) T3(1.6,-12.002) T4(2.4,-12.002) T5(3.2,-12.002) T10(7.201,-12.002) T11(8.001,-12.002) T12(8.801,-12.002) T13(9.601,-12.002) T14(10.401,-12.002) U1(0,-12.802) U2(0.8,-12.802) U3(1.6,-12.802) U4(2.4,-12.802) U5(3.2,-12.802) U10(7.201,-12.802) U11(8.001,-12.802) U12(8.801,-12.802) U13(9.601,-12.802) U14(10.401,-12.802)
  round 0.343 smd: F1(0,-4) F2(0.8,-4) F3(1.6,-4) F4(2.4,-4) F5(3.2,-4) F10(7.201,-4) F11(8.001,-4) F12(8.801,-4) F13(9.601,-4) F14(10.401,-4) G1(0,-4.801) G2(0.8,-4.801) G3(1.6,-4.801) G4(2.4,-4.801) G5(3.2,-4.801) G10(7.201,-4.801) G11(8.001,-4.801) G12(8.801,-4.801) G13(9.601,-4.801) G14(10.401,-4.801) H1(0,-5.601) H2(0.8,-5.601) H3(1.6,-5.601) H4(2.4,-5.601) H5(3.2,-5.601) H10(7.201,-5.601) H11(8.001,-5.601) H12(8.801,-5.601) H13(9.601,-5.601) H14(10.401,-5.601) J1(0,-6.401) J2(0.8,-6.401) J3(1.6,-6.401) J4(2.4,-6.401) J5(3.2,-6.401) J10(7.201,-6.401) J11(8.001,-6.401) J12(8.801,-6.401) J13(9.601,-6.401) J14(10.401,-6.401) K1(0,-7.201) K2(0.8,-7.201) K3(1.6,-7.201) K4(2.4,-7.201) K5(3.2,-7.201) K10(7.201,-7.201) K11(8.001,-7.201) K12(8.801,-7.201) K13(9.601,-7.201) K14(10.401,-7.201) L1(0,-8.001) L2(0.8,-8.001) L3(1.6,-8.001) L4(2.4,-8.001) L5(3.2,-8.001) L10(7.201,-8.001) L11(8.001,-8.001) L12(8.801,-8.001) L13(9.601,-8.001) L14(10.401,-8.001) M1(0,-8.801) M2(0.8,-8.801) M3(1.6,-8.801) M4(2.4,-8.801) M5(3.2,-8.801) M10(7.201,-8.801) M11(8.001,-8.801) M12(8.801,-8.801) M13(9.601,-8.801) M14(10.401,-8.801)
KB9022QD_LQFP128_14X14
  oval 1.753x0.203 smd: 1(0,0) 2(0,-0.4) 3(0,-0.8) 4(0,-1.2) 5(0,-1.6) 6(0,-2) 7(0,-2.4) 8(0,-2.8) 9(0,-3.2) 10(0,-3.6) 11(0,-4) 12(0,-4.4) 13(0,-4.8) 14(0,-5.2) 15(0,-5.6) 16(0,-6) 17(0,-6.4) 18(0,-6.8) 19(0,-7.2) 20(0,-7.6) 21(0,-8) 22(0,-8.4) 23(0,-8.8) 24(0,-9.2) 25(0,-9.6) 26(0,-10) 27(0,-10.4) 28(0,-10.8) 29(0,-11.2) 30(0,-11.6) 31(0,-12) 32(0,-12.4) 65(15.654,-12.4) 66(15.654,-12) 67(15.654,-11.6) 68(15.654,-11.2) 69(15.654,-10.8) 70(15.654,-10.4) 71(15.654,-10) 72(15.654,-9.6) 73(15.654,-9.2) 74(15.654,-8.8) 75(15.654,-8.4) 76(15.654,-8) 77(15.654,-7.6) 78(15.654,-7.2) 79(15.654,-6.8) 80(15.654,-6.4) 81(15.654,-6) 82(15.654,-5.6) 83(15.654,-5.2) 84(15.654,-4.8) 85(15.654,-4.4) 86(15.654,-4) 87(15.654,-3.6) 88(15.654,-3.2) 89(15.654,-2.8) 90(15.654,-2.4) 91(15.654,-2) 92(15.654,-1.6) 93(15.654,-1.2) 94(15.654,-0.8) 95(15.654,-0.4) 96(15.654,0)
  oval 0.203x1.753 smd: 33(1.627,-14.027) 34(2.027,-14.027) 35(2.427,-14.027) 36(2.827,-14.027) 37(3.227,-14.027) 38(3.627,-14.027) 39(4.027,-14.027) 40(4.427,-14.027) 41(4.827,-14.027) 42(5.227,-14.027) 43(5.627,-14.027) 44(6.027,-14.027) 45(6.427,-14.027) 46(6.827,-14.027) 47(7.227,-14.027) 48(7.627,-14.027) 49(8.027,-14.027) 50(8.427,-14.027) 51(8.827,-14.027) 52(9.227,-14.027) 53(9.627,-14.027) 54(10.027,-14.027) 55(10.427,-14.027) 56(10.827,-14.027) 57(11.227,-14.027) 58(11.627,-14.027) 59(12.027,-14.027) 60(12.427,-14.027) 61(12.827,-14.027) 62(13.227,-14.027) 63(13.627,-14.027) 64(14.027,-14.027) 97(14.027,1.627) 98(13.627,1.627) 99(13.227,1.627) 100(12.827,1.627) 101(12.427,1.627) 102(12.027,1.627) 103(11.627,1.627) 104(11.227,1.627) 105(10.827,1.627) 106(10.427,1.627) 107(10.027,1.627) 108(9.627,1.627) 109(9.227,1.627) 110(8.827,1.627) 111(8.427,1.627) 112(8.027,1.627) 113(7.627,1.627) 114(7.227,1.627) 115(6.827,1.627) 116(6.427,1.627) 117(6.027,1.627) 118(5.627,1.627) 119(5.227,1.627) 120(4.827,1.627) 121(4.427,1.627) 122(4.027,1.627) 123(3.627,1.627) 124(3.227,1.627) 125(2.827,1.627) 126(2.427,1.627) 127(2.027,1.627) 128(1.627,1.627)
L2N7002WT1G_SC70-3
  oval 0.711x0.889 smd: 1(0,0) 2(0.65,1.9) 3(-0.65,1.9)
L2N7002WT1G_SC-70-3
  oval 0.711x0.889 smd: 1(0,0) 2(-0.65,-1.9) 3(0.65,-1.9)
L03ESDL5V0CC3-2_SOT23-3
  oval 1.016x1.524 smd: 1(0,0) 2(0.965,2.083) 3(-0.965,2.083)
L_4X4X2_F_2P
  rect 1.194x3.708 smd: 1(0,0) 2(2.8,0)
L_5X5X3_M
  custom 0.54x0.54 smd: 1(0,0) 4(4.35,0)
  rect 0.762x0.508 smd: 2(0.699,0) 3(3.652,0)
L_5X5X3_M_2P
  rect 2.159x2.794 smd: 1(0,0) 2(4.35,0)
L_7X7X3_M
  custom 0.591x0.591 smd: 1(0,0) 4(6.05,0)
  rect 0.762x0.508 smd: 2(0.8,0) 3(5.25,0)
L_7X7X3_M_2P
  rect 2.362x3.505 smd: 1(0,0) 2(6.05,0)
LBSS139WT1G_SC70-3
  oval 0.711x0.889 smd: 1(0,0) 2(-0.65,-1.9) 3(0.65,-1.9)
LED_LTST-C191KFKT-2CA_2P
  rect 0.787x0.787 smd: 1(0,0) 2(1.5,0)
LED_LTW-C193TS5-C_2P
  rect 0.787x0.787 smd: 1(0,0) 2(1.5,0)
LMUN5113T1G_SOT323-3
  oval 0.711x0.889 smd: 1(0,0) 2(0.65,1.9) 3(-0.65,1.9)
LOTES_APCI0128-P005A_75P
  round 1.092 hole 1.092 unplated: (-0.75,-5.275)
  round 1.6 hole 1.6 unplated: (19.25,-5.275)
  oval 0.305x1.549 smd: 1(0,0) 2(0.25,-7.55) 3(0.5,0) 4(0.75,-7.55) 5(1,0) 6(1.25,-7.55) 7(1.5,0) 8(1.75,-7.55) 9(2,0) 10(2.25,-7.55) 11(2.5,0) 12(2.75,-7.55) 13(3,0) 14(3.25,-7.55) 15(3.5,0) 16(3.75,-7.55) 17(4,0) 18(4.25,-7.55) 19(4.5,0) 20(4.75,-7.55) 21(5,0) 22(5.25,-7.55) 23(5.5,0) 32(7.75,-7.55) 33(8,0) 34(8.25,-7.55) 35(8.5,0) 36(8.75,-7.55) 37(9,0) 38(9.25,-7.55) 39(9.5,0) 40(9.75,-7.55) 41(10,0) 42(10.25,-7.55) 43(10.5,0) 44(10.75,-7.55) 45(11,0) 46(11.25,-7.55) 47(11.5,0) 48(11.75,-7.55) 49(12,0) 50(12.25,-7.55) 51(12.5,0) 52(12.75,-7.55) 53(13,0) 54(13.25,-7.55) 55(13.5,0) 56(13.75,-7.55) 57(14,0) 58(14.25,-7.55) 59(14.5,0) 60(14.75,-7.55) 61(15,0) 62(15.25,-7.55) 63(15.5,0) 64(15.75,-7.55) 65(16,0) 66(16.25,-7.55) 67(16.5,0) 68(16.75,-7.55) 69(17,0) 70(17.25,-7.55) 71(17.5,0) 72(17.75,-7.55) 73(18,0) 74(18.25,-7.55) 75(18.5,0)
  rect 1.194x2.743 smd: 76(-1.1,-0.775) 77(19.6,-0.775)
LRB715FT1G_SOT323-3
  oval 0.711x0.889 smd: 1(0,0) 2(0.65,1.9) 3(-0.65,1.9)
LTC015EUBFS8TL_UMT3F
  oval 0.787x0.889 smd: 1(0,0) 2(-0.65,-1.6) 3(0.65,-1.6)
MC74VHC1G08DFT2G_SC70-5
  oval 0.381x0.711 smd: 1(0,0) 2(0.65,0) 3(1.3,0) 4(1.3,1.9) 5(0,1.9)
MMBT3904_NL_SOT23-3
  oval 1.016x1.524 smd: 1(0,0) 2(0.965,2.083) 3(-0.965,2.083)
MURAT_BLM15AX300SN1D_2P
  rect 0.457x0.508 smd: 1(0,0) 2(0.85,0)
MURAT_BLM15BD121SN1D_2P
  rect 0.457x0.508 smd: 1(0,0) 2(0.85,0)
MURAT_BLM15PX221SN1D_2P
  rect 0.457x0.508 smd: 1(0,0) 2(0.85,0)
MURAT_DLM0NSN900HY2D_4P
  rect 0.305x0.305 smd: 1(0,0) 2(0.6,0) 3(0.6,-0.5) 4(0,-0.5)
NC7SZ08P5X_NL_SC70-5
  oval 0.457x0.711 smd: 1(-0.65,-0.925) 2(0,-0.925) 3(0.65,-0.925) 4(0.65,0.925) 5(-0.65,0.925)
PJ2301_SOT23-3
  oval 1.016x1.524 smd: 1(0,0) 2(0.965,2.083) 3(-0.965,2.083)
PJT138KA_SOT363-6
  oval 0.457x0.508 smd: 1(0,0) 2(0.65,0) 3(1.3,0) 4(1.3,1.9) 5(0.65,1.9) 6(0,1.9)
PS_601012-008041_8P
  round 1.295 hole 0.889: 1(0,0) 2(1.02,1.1) 3(2.04,0) 4(3.06,1.1) 5(4.08,0) 6(5.1,1.1) 7(6.12,0) 8(7.14,1.1)
  oval 1.372x2.362 hole 0.61x1.6: 9(-4.43,-2.3) 10(-4.43,-10.1) 11(11.57,-2.3) 12(11.57,-10.1)
PSOT24C_SOT23-3
  oval 1.016x1.524 smd: 1(0,0) 2(0.965,2.083) 3(-0.965,2.083)
Q_N_DFN56-8-5
  oval 0.61x1.27 smd: 1(0,0) 2(1.27,0) 3(2.54,0) 4(3.81,0)
  custom 1.105x1.105 smd: 5(1.905,3.715)
R0201_0OHM
  rect 0.381x0.356 smd: 1(0,0) 2(0.584,0)
R0402_0OHM
  rect 0.508x0.559 smd: 1(0,0) 2(0.914,0)
R0603_0OHM
  rect 0.635x0.889 smd: 1(0,0) 2(1.397,0)
R0805_0OHM
  rect 0.813x1.397 smd: 1(0,0) 2(1.702,0)
R_0402
  rect 0.508x0.559 smd: 1(0,0) 2(0.914,0)
R_0603
  rect 0.635x0.889 smd: 1(0,0) 2(1.397,0)
R_0805
  rect 0.813x1.397 smd: 1(0,0) 2(1.702,0)
R_1206
  rect 1.016x1.651 smd: 1(0,0) 2(2.667,0)
R_1206_4P
  custom 0.476x0.476 smd: 1(0,0) 4(5.08,0)
  rect 1.397x0.381 smd: 2(1.206,0) 3(3.873,0)
RB715F_SOT323-3
  oval 0.813x0.914 smd: 1(0,0) 2(0.65,1.6) 3(-0.65,1.6)
RB751V-40TE17_SOD323-2
  rect 0.787x0.889 smd: 1(0,0) 2(0,-2.1)
RP_0804_8P4R
  oval 0.66x0.254 smd: 1(0,0) 2(0,-0.5) 3(0,-1) 4(0,-1.5) 5(1.15,-1.5) 6(1.15,-1) 7(1.15,-0.5) 8(1.15,0)
RT3661ABGQW_WQFN40_5X5
  oval 0.889x0.203 smd: 1(0,0) 2(0,-0.4) 3(0,-0.8) 4(0,-1.2) 5(0,-1.6) 6(0,-2) 7(0,-2.4) 8(0,-2.8) 9(0,-3.2) 10(0,-3.6) 21(5.1,-3.6) 22(5.1,-3.2) 23(5.1,-2.8) 24(5.1,-2.4) 25(5.1,-2) 26(5.1,-1.6) 27(5.1,-1.2) 28(5.1,-0.8) 29(5.1,-0.4) 30(5.1,0)
  oval 0.203x0.889 smd: 11(0.75,-4.35) 12(1.15,-4.35) 13(1.55,-4.35) 14(1.95,-4.35) 15(2.35,-4.35) 16(2.75,-4.35) 17(3.15,-4.35) 18(3.55,-4.35) 19(3.95,-4.35) 20(4.35,-4.35) 31(4.35,0.75) 32(3.95,0.75) 33(3.55,0.75) 34(3.15,0.75) 35(2.75,0.75) 36(2.35,0.75) 37(1.95,0.75) 38(1.55,0.75) 39(1.15,0.75) 40(0.75,0.75)
  rect 3.378x3.378 smd: 41(2.55,-1.8)
RT3662EBGQW_WQFN32_4X4
  oval 0.838x0.203 smd: 1(0,0) 2(0,-0.4) 3(0,-0.8) 4(0,-1.2) 5(0,-1.6) 6(0,-2) 7(0,-2.4) 8(0,-2.8) 17(4.15,-2.8) 18(4.15,-2.4) 19(4.15,-2) 20(4.15,-1.6) 21(4.15,-1.2) 22(4.15,-0.8) 23(4.15,-0.4) 24(4.15,0)
  oval 0.203x0.838 smd: 9(0.675,-3.475) 10(1.075,-3.475) 11(1.475,-3.475) 12(1.875,-3.475) 13(2.275,-3.475) 14(2.675,-3.475) 15(3.075,-3.475) 16(3.475,-3.475) 25(3.475,0.675) 26(3.075,0.675) 27(2.675,0.675) 28(2.275,0.675) 29(1.875,0.675) 30(1.475,0.675) 31(1.075,0.675) 32(0.675,0.675)
  rect 2.692x2.692 smd: 33(2.075,-1.4)
RT8207PGQW_WQFN20_3X3
  oval 0.203x0.889 smd: 1(0,0) 2(0.4,0) 3(0.8,0) 4(1.2,0) 5(1.6,0) 11(1.6,3.1) 12(1.2,3.1) 13(0.8,3.1) 14(0.4,3.1) 15(0,3.1)
  oval 0.889x0.203 smd: 6(2.35,0.75) 7(2.35,1.15) 8(2.35,1.55) 9(2.35,1.95) 10(2.35,2.35) 16(-0.75,2.35) 17(-0.75,1.95) 18(-0.75,1.55) 19(-0.75,1.15) 20(-0.75,0.75)
  rect 1.702x1.702 smd: 21(0.8,1.55)
RTL8111GS-CG_QFN32_4X4
  oval 0.203x0.914 smd: 1(0,0) 2(0.4,0) 3(0.8,0) 4(1.2,0) 5(1.6,0) 6(2,0) 7(2.4,0) 8(2.8,0) 17(2.8,4.077) 18(2.4,4.077) 19(2,4.077) 20(1.6,4.077) 21(1.2,4.077) 22(0.8,4.077) 23(0.4,4.077) 24(0,4.077)
  oval 0.914x0.203 smd: 9(3.438,0.639) 10(3.438,1.039) 11(3.438,1.438) 12(3.438,1.838) 13(3.438,2.239) 14(3.438,2.639) 15(3.438,3.039) 16(3.438,3.438) 25(-0.639,3.438) 26(-0.639,3.039) 27(-0.639,2.639) 28(-0.639,2.239) 29(-0.639,1.838) 30(-0.639,1.438) 31(-0.639,1.039) 32(-0.639,0.639)
  rect 2.692x2.692 smd: 33(1.4,2.039)
RTS5146-GR_QFN24_4X4
  oval 0.889x0.254 smd: 1(0,0) 2(0,-0.5) 3(0,-1) 4(0,-1.5) 5(0,-2) 6(0,-2.5) 13(4.1,-2.5) 14(4.1,-2) 15(4.1,-1.5) 16(4.1,-1) 17(4.1,-0.5) 18(4.1,0)
  oval 0.254x0.889 smd: 7(0.8,-3.3) 8(1.3,-3.3) 9(1.8,-3.3) 10(2.3,-3.3) 11(2.8,-3.3) 12(3.3,-3.3) 19(3.3,0.8) 20(2.8,0.8) 21(2.3,0.8) 22(1.8,0.8) 23(1.3,0.8) 24(0.8,0.8)
  rect 2.261x2.261 smd: 25(2.05,-1.25)
S-5711ACDL-M3T1S_SOT23-3
  oval 1.016x1.524 smd: 1(0,0) 2(0.965,2.083) 3(-0.965,2.083)
SAMTE_ASP-136446-07-B_20P-T
  oval 0.737x2.794 smd: 1(0,0) 2(0,4.07) 3(1.27,0) 4(1.27,4.07) 5(2.54,0) 6(2.54,4.07) 7(3.81,0) 8(3.81,4.07) 9(5.08,0) 10(5.08,4.07) 11(6.35,0) 12(6.35,4.07) 13(7.62,0) 14(7.62,4.07) 15(8.89,0) 16(8.89,4.07) 17(10.16,0) 18(10.16,4.07) 19(11.43,0) 20(11.43,4.07)
SHORTPADS
  custom 0.19x0.19 smd: 1(-0.483,0) 2(0.483,0)
SINGA_2DC3169-000111F_5P-T
  oval 2.388x1.194 hole 2.007x0.787: 1(0,0)
  oval 1.194x1.803 hole 0.787x1.397: 2(-4.9,2.01) 5(4.9,2.01)
  oval 1.397x1.041 hole 0.991x0.66: 3(-5,7.13) 4(5,7.13)
SINGA_2SJ3095-140111F_6P-T
  oval 1.092x1.803 hole 0.61x1.397: 1(0,0) 2(-9.55,5.5) 3(0,7.8) 4(-9.55,8.4) 5(-9.55,0) 6(-9.55,2.75) 7(0,4.1)
SN74AHC1G08DCKR_SC70-5
  oval 0.381x1.295 smd: 1(0,0.15) 2(0.65,0.15) 3(1.3,0.15) 4(1.3,1.89) 5(0,1.89)
SN74LVC1G07DCKR_SC70-5
  oval 0.381x0.864 smd: 1(0,0) 2(0.65,0) 3(1.3,0) 4(1.3,1.74) 5(0,1.74)
SUYIN_125022HB008M200ZL_8P-T
  oval 0.787x1.295 smd: 1(0,0) 2(-1.25,0) 3(-2.5,0) 4(-3.75,0) 5(-5,0) 6(-6.25,0) 7(-7.5,0) 8(-8.75,0)
  oval 1.041x1.651 hole 0.66x1.245: 9(-10.5,-2.85) 10(-10.5,-6.325) 11(1.75,-2.85) 12(1.75,-6.325)
SW_NTC325-EK1J-A160T_3P
  oval 0.94x1.143 smd: 1(0,0) 3(2.45,0)
  oval 0.61x1.143 smd: 2(1.225,0)
  oval 1.194x0.711 hole 0.889x0.406: 4(-0.575,-2.625) 5(3.025,-2.625)
  custom 0.394x0.394 hole 0.889: 6(-0.9,-1.525) 7(3.35,-1.525)
SY6288C20AAC_SOT23-5
  oval 0.559x0.787 smd: 1(0,0) 2(0.95,0) 3(1.9,0) 4(1.9,2.4) 5(0,2.4)
SY6288D20AAC_SOT23-5
  oval 0.559x0.787 smd: 1(0,0) 2(0.95,0) 3(1.9,0) 4(1.9,2.4) 5(0,2.4)
SY8286BRAC_QFN20_3X3
  oval 0.889x0.254 smd: 1(0,0) 2(0,-0.45) 3(0,-0.9) 4(0,-1.35) 5(0,-1.8) 11(3.1,-1.8) 12(3.1,-1.35) 13(3.1,-0.9) 14(3.1,-0.45) 15(3.1,0)
  oval 0.254x0.889 smd: 6(0.65,-2.45) 7(1.1,-2.45) 8(1.55,-2.45) 9(2,-2.45) 10(2.45,-2.45) 16(2.45,0.65) 17(2,0.65) 18(1.55,0.65) 19(1.1,0.65) 20(0.65,0.65)
  rect 0.991x0.991 smd: 21(1.55,-0.9)
SY8286CRAC_QFN20_3X3
  oval 0.889x0.254 smd: 1(0,0) 2(0,-0.45) 3(0,-0.9) 4(0,-1.35) 5(0,-1.8) 11(3.1,-1.8) 12(3.1,-1.35) 13(3.1,-0.9) 14(3.1,-0.45) 15(3.1,0)
  oval 0.254x0.889 smd: 6(0.65,-2.45) 7(1.1,-2.45) 8(1.55,-2.45) 9(2,-2.45) 10(2.45,-2.45) 16(2.45,0.65) 17(2,0.65) 18(1.55,0.65) 19(1.1,0.65) 20(0.65,0.65)
  rect 0.991x0.991 smd: 21(1.55,-0.9)
SY8286RAC_QFN20_3X3
  oval 0.889x0.254 smd: 1(0,0) 2(0,-0.45) 3(0,-0.9) 4(0,-1.35) 5(0,-1.8) 11(3.1,-1.8) 12(3.1,-1.35) 13(3.1,-0.9) 14(3.1,-0.45) 15(3.1,0)
  oval 0.254x0.889 smd: 6(0.65,-2.45) 7(1.1,-2.45) 8(1.55,-2.45) 9(2,-2.45) 10(2.45,-2.45) 16(2.45,0.65) 17(2,0.65) 18(1.55,0.65) 19(1.1,0.65) 20(0.65,0.65)
  rect 0.991x0.991 smd: 21(1.55,-0.9)
SY8288RAC_QFN20_3X3
  oval 0.889x0.254 smd: 1(0,0) 2(0,-0.45) 3(0,-0.9) 4(0,-1.35) 5(0,-1.8) 11(3.1,-1.8) 12(3.1,-1.35) 13(3.1,-0.9) 14(3.1,-0.45) 15(3.1,0)
  oval 0.254x0.889 smd: 6(0.65,-2.45) 7(1.1,-2.45) 8(1.55,-2.45) 9(2,-2.45) 10(2.45,-2.45) 16(2.45,0.65) 17(2,0.65) 18(1.55,0.65) 19(1.1,0.65) 20(0.65,0.65)
  rect 0.991x0.991 smd: 21(1.55,-0.9)
TAI-T_HCB2012KF-121T50_2P
  rect 0.813x1.397 smd: 1(0,0) 2(1.702,0)
TAIMA_IH-160_24P
  oval 0.61x2.362 smd: 1(0,0) 2(1,0) 3(2,0) 4(3,0) 5(4,0) 6(5,0) 7(6,0) 8(7,0) 9(8,0) 10(9,0) 11(10,0) 12(11,0) 13(11,8.35) 14(10,8.35) 15(9,8.35) 16(8,8.35) 17(7,8.35) 18(6,8.35) 19(5,8.35) 20(4,8.35) 21(3,8.35) 22(2,8.35) 23(1,8.35) 24(0,8.35)
TPC12
  round 0.305 smd: 1(0,0)
W25Q64DWSSIG_SO8
  oval 0.635x1.676 smd: 1(0,0) 2(1.27,0) 3(2.54,0) 4(3.81,0) 5(3.81,7.25) 6(2.54,7.25) 7(1.27,7.25) 8(0,7.25)
Y_X1A000141000200_2P
  rect 0.991x1.803 smd: 1(0,0) 2(2.5,0)
Y_X3S048000D81H-W_4P
  rect 1.397x1.194 smd: 1(0,0) 2(2.2,0) 3(2.2,1.7) 4(0,1.7)
Y_XRCGB25M000F2P18R0_4P
  rect 0.762x0.711 smd: 1(0,0) 2(1.35,0) 3(1.35,1) 4(0,1)
Y_XRCGB27M000F2P18R0_4P
  rect 0.762x0.711 smd: 1(0,0) 2(1.35,0) 3(1.35,1) 4(0,1)
YSCLAMP0524P_SLP2510P8-10-9
  oval 0.203x0.686 smd: 1(0,0) 2(0.5,0) 4(1.5,0) 5(2,0) 6(2,0.875) 7(1.5,0.875) 8(0.5,0.875) 9(0,0.875)
  oval 0.406x1.549 smd: 3(1,0.438)

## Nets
0.95VS_GATE: C859.1 Q19.4 Q84.1 R947.2
0.95VS_PWR_EN#: Q83.2 Q84.2 RP4.6 U11.99
0.775VALW_GATE: QC20.2 QC21.2 RC151.2 UC26.7
1.8VALW_PWR_EN#: Q401.5 Q401.6 R945.2
1.8VS_PWR_EN: R937.1 R949.2 U11.98
3V/5VALW_PG: C2155.2 PR406.2 PR2005.1 PU401.9 PU402.9 Q401.2 R922.2
3V/5VALW_PG_R: R922.1 U11.101
3V_FB: PC402.1 PU401.13
3V_FB_1: PC402.2 PR403.1
3V_SN: PC412.1 PR405.2
3VGS_EN#: CV83.1 QV16.2 RV43.2
5V_3V_EN: PC428.1 PR410.2 PR411.2 PR412.1 PU401.12 PU402.12
5V_FB: PC413.1 PU402.13
5V_FB_1: PC413.2 PR407.1
5V_SN: PC426.1 PR409.2
+0.6V_DDR_VREFCA: CD210.2 CD211.2 CD213.2 JDIMM1.164 RD208.1 RD209.2
+0.6VS: CD207.1 CD208.1 JDIMM1.258 PJ503.2 R933.1
+0.6VSP: PC506.1 PC507.1 PJ503.1 PU501.2 PU501.20
+0.95VALW: C853.2 CC70.1 CC71.1 CV291.1 PJ601.2 Q19.5 Q19.6 Q19.7 Q19.8 RC101.2 U1895V.1 U1895V.2 UC1.AJ11 UC1.AL11 UC1.AL13
+0.95VALWP: PC608.1 PC609.1 PC610.1 PC611.1 PC612.1 PC11225.1 PC11226.1 PJ601.1 PL602.2 PR2221.1
+0.95VGS: CV30.1 CV32.2 CV33.1 CV54.1 CV55.1 CV56.1 CV57.1 CV58.1 CV59.1 CV60.1 CV120.1 CV121.1 LV8.1 RV1.2 RV3.2 RV31.1 RV56.2 U1895V.13 U1895V.14 UV1.AD14 UV1.L23 UV1.L24 UV1.L25 UV1.L26 UV1.M22 UV1.N22 UV1.N23 UV1.N24 UV1.R22 UV1.T22 UV1.U22 UV1.V22
+0.95VS: C854.2 C855.1 CC58.1 CC59.1 CC60.1 CC61.1 CC62.1 CC63.1 CC64.1 CC65.1 CC66.1 CC67.1 CC68.1 CC69.1 Q19.1 Q19.2 Q19.3 R935.1 RC1.1 RC89.2 UC1.AJ21 UC1.AJ23 UC1.AJ25 UC1.AJ27 UC1.AL23 UC1.AL25 UC1.AL27 UC1.AL29
+0.775VALW: CC130.2 PJ1001.2 QC20.1 QC22.6
+0.775VALWP: PC11216.1 PJ1001.1 PU903.4
+1.2V: CC20.1 CC21.1 CC22.1 CC23.1 CC24.1 CC25.1 CC26.1 CC27.1 CC28.1 CC29.1 CC30.1 CC31.1 CC32.1 CC33.1 CC34.1 CC35.1 CC36.1 CC37.1 CC38.1 CC39.1 CC40.1 CC41.1 CC42.1 CC43.1 CD212.2 CD214.1 CD215.1 CD216.1 CD217.1 CD218.1 CD219.1 CD220.1 CD221.1 CD222.1 CD223.1 CD224.1 CD225.1 CD226.1 CD227.1 CD228.1 CD229.1 CD230.1 JDIMM1.111 JDIMM1.112 JDIMM1.117 JDIMM1.118 JDIMM1.123 JDIMM1.124 JDIMM1.129 JDIMM1.130 JDIMM1.135 JDIMM1.136 JDIMM1.141 JDIMM1.142 JDIMM1.147 JDIMM1.148 JDIMM1.153 JDIMM1.154 JDIMM1.159 JDIMM1.160 JDIMM1.163 PJ501.2 PJ502.2 RC3.2 RC4.1 RD201.1 RD208.2 UC1.AA35 UC1.AC32 UC1.AC37 UC1.AE32 UC1.AE35 UC1.AG32 UC1.AG37 UC1.AJ32 UC1.AJ35 UC1.AL32 UC1.AL37 UC1.AR35 UC1.J35 UC1.L32 UC1.L37 UC1.N35 UC1.R37 UC1.U32 UC1.U35 UC1.W32 UC1.W37
+1.2VP: PC509.1 PC510.1 PC511.1 PC512.1 PC513.1 PC514.1 PJ501.1 PJ502.1 PL502.1 PL502.2 PR506.2 PU501.5 PU501.19
+1.8VALW: C856.1 CC53.1 CC54.1 CV301.1 PJ802.2 R946.1 RC60.1 U18.1 U18.2 U1895V.6 U1895V.7 UC1.AJ13 UC1.AL15
+1.8VALWP: PC2004.1 PC2007.1 PJ802.1 PR2001.1 PU2001.6
+1.8VGS: CV26.1 CV27.1 CV31.2 CV38.1 CV39.1 CV46.1 CV179.1 LV2.1 LV3.1 LV6.1 LV7.1 PR1005.1 PR1006.2 PR1016.2 RV8.1 RV11.1 RV15.1 RV28.1 RV57.2 RV81.2 RV82.2 RV84.2 RV87.2 RV152.2 U1895V.8 U1895V.9 UV1.AF14 UV1.AM30
+1.8VS: C857.1 C858.1 CA40.2 CC14.1 CC45.1 CC46.1 CC47.1 CC48.1 CC49.1 CC50.1 JHDT1.1 JHDT1.19 PR818.2 QC1.2 QC2.2 QC2.5 QC17.2 QC17.5 R940.2 RA6.2 RA53.2 RC13.1 RC14.1 RC25.2 RC146.1 RC147.1 RPC1.5 RPC1.6 RPC1.7 RPC1.8 RPC3.5 RPC4.5 RPC4.6 RPC4.7 RPC4.8 RPC11.1 RPC11.2 RPC11.3 RPC14.6 RPC14.7 RPC14.8 UA1.29 UC1.AJ15 UC1.AL17 UC1.AM13 UC2.8 UC21.5
+1.8VS_R: R940.1 U18.7 U18.8
+1.35VGSP: PC907.1 PC908.1 PC909.1 PC910.1 PC911.1 PJ902.1 PL901.2 PR905.1
+1.35VS_VRAM: CV40.1 CV41.1 CV42.1 CV43.1 CV44.1 CV45.1 CV47.1 CV48.1 CV49.1 CV50.1 CV51.1 CV52.1 CV53.1 CV160.1 CV161.1 CV162.1 CV163.1 CV164.1 CV165.1 CV166.1 CV167.1 CV168.1 CV169.1 CV170.1 CV171.1 CV172.1 CV173.1 CV174.1 CV175.1 CV176.1 CV177.1 CV178.1 CV187.1 CV188.1 CV373.1 CV374.1 CV375.1 CV376.1 CV377.1 CV378.1 CV379.1 CV380.1 CV381.1 CV382.1 CV383.1 CV384.1 CV385.1 CV386.1 CV387.1 CV388.1 CV389.1 PJ902.2 RV32.1 RV33.1 RV79.1 RV80.1 RV85.1 RV86.1 RV380.1 UV1.H13 UV1.H16 UV1.H19 UV1.J9 UV1.J10 UV1.J23 UV1.J24 UV1.K9 UV1.K10 UV1.K23 UV1.K24 UV1.L11 UV1.L12 UV1.L13 UV1.L20 UV1.L21 UV1.L22 UV7.B1 UV7.B3 UV7.B12 UV7.B14 UV7.C5 UV7.C10 UV7.D1 UV7.D3 UV7.D11 UV7.D12 UV7.D14 UV7.E5 UV7.E10 UV7.F1 UV7.F3 UV7.F12 UV7.F14 UV7.G1 UV7.G2 UV7.G4 UV7.G11 UV7.G13 UV7.G14 UV7.H3 UV7.H12 UV7.K3 UV7.K12 UV7.L1 UV7.L2 UV7.L4 UV7.L11 UV7.L13 UV7.L14 UV7.M1 UV7.M3 UV7.M12 UV7.M14 UV7.N5 UV7.N10 UV7.P1 UV7.P3 UV7.P11 UV7.P12 UV7.P14 UV7.R5 UV7.R10 UV7.T1 UV7.T3 UV7.T12 UV7.T14 UV8.B1 UV8.B3 UV8.B12 UV8.B14 UV8.C5 UV8.C10 UV8.D1 UV8.D3 UV8.D11 UV8.D12 UV8.D14 UV8.E5 UV8.E10 UV8.F1 UV8.F3 UV8.F12 UV8.F14 UV8.G1 UV8.G2 UV8.G4 UV8.G11 UV8.G13 UV8.G14 UV8.H3 UV8.H12 UV8.K3 UV8.K12 UV8.L1 UV8.L2 UV8.L4 UV8.L11 UV8.L13 UV8.L14 UV8.M1 UV8.M3 UV8.M12 UV8.M14 UV8.N5 UV8.N10 UV8.P1 UV8.P3 UV8.P11 UV8.P12 UV8.P14 UV8.R5 UV8.R10 UV8.T1 UV8.T3 UV8.T12 UV8.T14
+2.5V: CD203.1 CD204.1 CD205.1 CD206.1 JDIMM1.257 JDIMM1.259 PJ804.2
+2.5VP: PC2005.1 PC2010.1 PJ804.1 PR2004.1 PU2002.6
+3V_LAN: CL2.1 CL3.1 CL20.1 CL21.1 RL1.1 RL17.2 RL18.2 UL2.11 UL2.32
+3VALW: C832.1 C849.1 C850.1 C2152.1 CC10.1 CC51.1 CC52.1 CL1.2 PC614.1 PC913.1 PC11217.1 PJ401.2 PJ801.1 PJ803.1 PJ1000.1 PR204.2 PR607.1 PR611.1 PR2009.1 PU601.15 PU901.15 PU903.5 PU903.6 PU903.7 PU903.8 QV16.3 R198.2 R271.2 R273.2 R931.2 RC34.1 RC35.1 RC36.1 RC44.1 RC45.1 RC46.1 RC63.1 RC69.1 RC81.1 RC83.1 RC85.1 RC152.2 RL18.1 U282.2 U381.6 U381.7 UA1.16 UC1.AJ17 UC1.AL19 UC23.5 UC24.5
+3VALW_3VS: J5.2 U381.8 U381.9
+3VALW_EC: C180.1 C181.1 C182.1 C183.1 L20.1 R189.2 R192.2 R932.2 U11.9 U11.22 U11.33 U11.96 U11.125
+3VALWP: PC407.1 PC408.1 PC409.1 PC410.1 PJ401.1 PL402.3 PL402.4 PR403.2 PU401.14
+3VDD_CODEC: CA44.1 CA62.1 RA51.2 RA59.1 UA1.1
+3VGS: CV36.1 CV37.1 LV4.1 PR1002.1 QV1.2 QV1.5 QV16.1 RPV34.1 RPV34.2 RPV34.3 RV5.1 RV6.1 RV42.1 RV91.2 RV154.1 RV162.1 RV3151.2 UV2.5
+3VL: C179.1 PJP402.2 PR108.2 PR203.2 PR406.1 R189.1 RP3.5 RP3.6 RP4.1 RP4.2 RP4.3 U11.111
+3VLP: PC411.1 PJP402.1 PU401.16 PU401.17
+3VS: C217.1 C851.1 C852.1 CD201.2 CD202.2 CR1.1 CR2.1 J5.1 JDIMM1.255 JEDP1.29 PR813.1 PR835.2 Q201.3 QH5.1 QH15.2 QH15.5 QH17.2 R212.1 R214.2 R242.1 R279.1 R280.1 RA59.2 RC18.2 RC21.2 RC41.1 RC75.1 RC77.1 RC79.1 RC90.1 RC120.1 RC133.1 RC144.1 RC145.1 RC156.1 RC158.1 RC162.2 RC163.2 RD202.1 RD203.1 RD204.1 RH29.1 RH30.1 RL8.1 RP3.7 RP3.8 RPC12.1 RPC12.3 RPC13.3 U202.5 U203.5 UC22.5 UR1.5 UR1.6 UR1.8
+3VS_APU: CC44.1 CC76.1 RC120.2 UC1.AJ19 UC1.AL21
+3VS_CMOS: C202.1 C203.1 JEDP1.1 Q201.1 R212.2
+3VS_WLAN: C243.1 C244.1 JWLAN1.2 JWLAN1.4 JWLAN1.72 JWLAN1.74 R242.2
+5V_DISPLAY: CH11.1 DH1.4 DH1.7 JHDMI1.18 RH27.1 RH28.1 UH1.3
+5V_HDD: C232.1 C237.1 C238.1 C239.1 JHDD1.1 JHDD1.2 JHDD1.3 JHDD1.4 R233.2
+5V_ODD: C2147.1 C2148.1 C2149.1 JODD2.8 JODD2.9 JODD2.10 R420.2
+5VALW: C305.1 C843.1 C844.1 C861.1 PC2003.1 PC2006.1 PJ403.2 PR504.1 PR505.1 PR801.2 PR837.2 PR1029.2 PR1033.2 PU2001.4 PU2002.4 R194.2 R278.2 R377.2 R934.1 R945.1 R947.1 RC150.1 RC151.1 RC153.2 RV44.1 U18.4 U301.5 U381.1 U381.2 UC26.8
+5VALW_5VS: J4.2 U381.13 U381.14
+5VALWP: PC420.1 PC421.1 PC422.1 PC423.1 PC424.1 PC425.1 PJ403.1 PL404.3 PL404.4 PR407.2 PU402.14
+5VDDA_CODEC: CA55.1 CA58.1 RA48.1 UA1.20
+5VLP: PC427.1 PJP404.1 PU402.15
+5VS: C371.2 C845.1 C846.1 CH12.1 DA3.5 J4.1 R233.1 R371.1 R420.1 RA2.2 RA48.2 UH1.1
+5VS_FAN: JFAN1.4 R371.2
+5VS_PVDD: CA1.2 CA49.1 CA53.1 CA66.2 RA2.1 UA1.34 UA1.39
+8.4V_VMB: PC201.1 PF201.2 PL201.1 PL202.1
+12.6V_BATT+: PC202.1 PC761.1 PC775.1 PC776.1 PL201.2 PL202.2 PQ710.3 PR745.2 PR765.4
+12.6VB_DDR: PC501.1 PC502.1 PC503.1 PC504.1 PL501.2 PQ501.5 PR507.1
+17.4V_BATT_CHG: PC779.2 PL700.2 PQ705.1 PQ705.2 PQ705.3 PR765.1
+19V_APDIN: PC101.1 PC102.1 PF101.2 PL101.1 PL102.1
+19V_P1: PQ707.3 PQ712.1 PQ712.2 PQ712.3 PQ740.1 PQ740.2 PQ740.3 PR737.2 PR763.1
+19V_P2: PQ712.5 PR703.1
+19V_VIN: PC103.1 PC104.1 PD703.3 PL101.2 PL102.2 PQ740.5 PR729.1
+19VB_1V: PC604.1 PC605.1 PC606.1 PJ602.2 PU601.2 PU601.3 PU601.4 PU601.5
+19VB_3V: PC403.1 PC404.1 PC405.1 PL401.2 PU401.2 PU401.3 PU401.4 PU401.5
+19VB_5V: PC414.1 PC415.1 PC416.1 PC417.1 PL403.2 PR451.1 PU402.2 PU402.3 PU402.4 PU402.5
+19VB_APU: PC802.1 PC803.1 PC823.1 PC824.1 PC831.1 PC832.1 PC943.1 PC944.1 PC11224.1 PL801.1 PL802.1 PQ801.5 PQ803.5 PR806.1
+19VB_CHG: PC705.1 PC760.1 PC762.1 PC765.1 PL301.2 PQ704.5
+VCC_IO2: C823.1 R932.1 U11.124
+VDD_CT: CV61.1 CV62.1 CV63.1 LV3.2 UV1.AA20 UV1.AA21 UV1.AB20 UV1.AB21
+VDDCR_FCH_ALW: CC55.1 CC56.1 CC57.1 CC131.2 CC132.1 CC133.1 CC134.2 CC135.2 QC19.1 QC21.1 UC1.AR4 UC1.AR5 UC1.AR7 UC1.AU7
+VDDR3: CV64.1 CV65.1 CV66.1 CV123.1 LV4.2 UV1.AA17 UV1.AA18 UV1.AB17 UV1.AB18
